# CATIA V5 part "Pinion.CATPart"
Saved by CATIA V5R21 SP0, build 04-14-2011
Part number: Part3
Bounding box of the stored display mesh (mm): x -15 to 0, y -25 to 25, z 10.489 to 60.125
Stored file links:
  D:\CATIA V5R21 E-RESOURCES\CATIA-V5R21\catia-v5r21-Prts\c16_catia_v5r21_prt\Rack Joint-(Fig16-57)\Pinion.CATPart
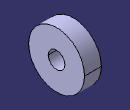
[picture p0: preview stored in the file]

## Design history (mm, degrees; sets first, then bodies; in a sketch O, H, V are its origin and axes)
Body1 (main body)
  Sketch1 on yz-plane, origin (0, 0, 0), H (0, 1, 0), V (0, 0, 1)
    reference intersected line E1 through (0, 0) direction (-1, 0) from xy-plane
    reference intersected line E3 through (0, 0) direction (0, 1) from zx-plane
    reference intersected line E4 through (0, 0) direction (-1, 0) from xy-plane
    reference intersected line E6 through (0, 0) direction (0, 1) from zx-plane
    reference intersected line E7 through (0, 0) direction (-1, 0) from xy-plane
    reference intersected line E9 through (0, 0) direction (0, 1) from zx-plane
    circle A1 centre (0, 35.3069) radius 25
    point P1 (0, 35.3069)
    circle A2 centre (0, 35.3069) radius 7.5
    radius A1 = 25
    radius A2 = 7.5
    vertical: E3 V, E6 V, E9 V
    horizontal: E1 H, E4 H, E7 H
    coincidence: P1 V
  Pad1: profile Sketch1, direction (1, 0, 0), length -15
